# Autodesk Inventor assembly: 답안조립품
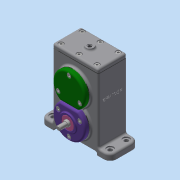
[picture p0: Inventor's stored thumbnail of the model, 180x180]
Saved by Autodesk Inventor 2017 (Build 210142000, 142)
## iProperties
Part Number: 답안조립품
Material: 일반
Document SubType Name: Assembly
Designer: mrc
Mass: 1460.95 g
Surface Area: 1575.48 cm^2
Volume: 385.032 cm^3
Density: 3.79437 g/cm^3
Author: mrc
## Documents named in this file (24)
- C:\Users\mrc\Desktop\600506V1023\답안조립품.iam
- C:\Users\mrc\Desktop\600506V1023\본체.ipt
- C:\Users\mrc\Desktop\600506V1023\개스킷 A.ipt
- C:\Users\mrc\Desktop\600506V1023\개스킷 B.ipt
- C:\Users\mrc\Desktop\600506V1023\개스킷 C.ipt
- C:\Users\mrc\Desktop\600506V1023\베어링 6001.ipt
- 베어링 6001.ipt
- C:\Users\mrc\Desktop\600506V1023\베어링 6002.ipt
- 베어링 6002.ipt
- C:\Users\mrc\Desktop\600506V1023\볼트 M4.ipt
- C:\Users\mrc\Desktop\600506V1023\스퍼기어 A.ipt
- C:\Users\mrc\Desktop\600506V1023\스퍼기어 B.ipt
- C:\Users\mrc\Desktop\600506V1023\오일 실 10 20 7.ipt
- C:\Users\mrc\Desktop\600506V1023\오일 실 12 22 7.ipt
- C:\Users\mrc\Desktop\600506V1023\축 A.ipt
- C:\Users\mrc\Desktop\600506V1023\축 B.ipt
- C:\Users\mrc\Desktop\600506V1023\칼라.ipt
- C:\Users\mrc\Desktop\600506V1023\커버 A.ipt
- C:\Users\mrc\Desktop\600506V1023\커버 B.ipt
- C:\Users\mrc\Desktop\600506V1023\커버 C.ipt
- C:\Users\mrc\Desktop\600506V1023\커버 D.ipt
- C:\Users\mrc\Desktop\600506V1023\커버 E.ipt
- C:\Users\mrc\Desktop\600506V1023\키 4 x 4 x 12.ipt
- C:\Users\mrc\Desktop\600506V1023\키 5 x 5 x 12.ipt
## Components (5 placed, 3 different names)
1. 개스킷 A:1
2. 개스킷 B:1
3. 개스킷 C:1
4. 개스킷 B:2
5. 개스킷 B:3
